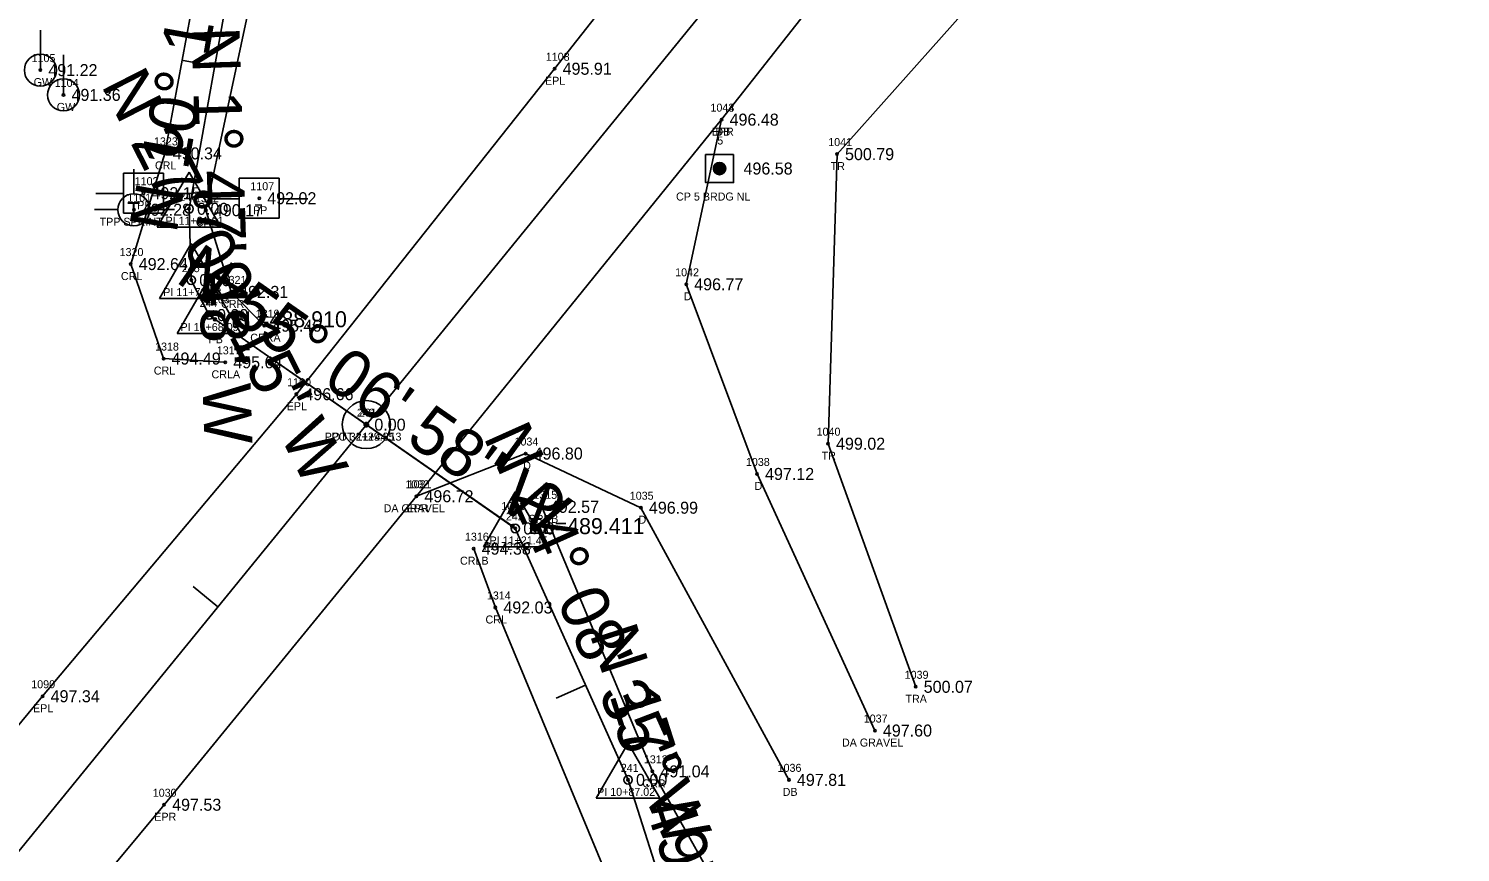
# Model space of a CAD drawing. Extents: x 1649047 to 1650429, y 896228 to 898747.
# Drawn here: x 1649581.4 to 1649760.2, y 896937.8 to 897040.7 of the extents above; entities that cross this region are included whole.
import ezdxf

# ---------------------------------------------------------------- set-up
doc = ezdxf.new("R2010")
doc.units = 0
for name, color, linetype in [('RD_EX_DR_Pipe', 7, 'Continuous'), ('RD_EX_DR_Pipe_txCode', 7, 'Continuous'), ('RD_EX_Driveway', 7, 'Continuous'), ('RD_EX_Driveway_txCode', 7, 'Continuous'), ('RD_EX_H2O', 7, 'Continuous'), ('RD_EX_H2O_txCode', 7, 'Continuous'), ('RD_EX_Road', 7, 'Continuous'), ('RD_EX_Road_txCode', 7, 'Continuous'), ('RD_EX_TX_Driveway_ELEV', 7, 'Continuous'), ('RD_EX_TX_H2O_ELEV', 7, 'Continuous'), ('RD_EX_TX_Road_ELEV', 7, 'Continuous'), ('RD_EX_TX_UT_ELEV', 7, 'Continuous'), ('RD_EX_TX_VEG_ELEV', 7, 'Continuous'), ('RD_EX_UT', 7, 'Continuous'), ('RD_EX_UT_txCode', 7, 'Continuous'), ('RD_EX_VEG', 7, 'Continuous'), ('RD_EX_VEG_txCode', 7, 'Continuous'), ('RD_HC_Cl', 7, 'Continuous'), ('RD_HC_Data', 7, 'Continuous'), ('RD_HC_Data_Tic', 7, 'Continuous'), ('RD_HC_Survey', 7, 'Continuous'), ('RD_HC_Survey_ELEV', 7, 'Continuous'), ('RD_HC_Survey_txCode', 7, 'Continuous'), ('RD_HC_txCode', 7, 'Continuous'), ('RD_SMD_Locator', 7, 'Continuous'), ('RD_TX_Pipe_ElevEX', 7, 'Continuous')]:
    doc.layers.add(name, color=color, linetype=linetype)

msp = doc.modelspace()

# ---------------------------------------------------------------- linework, layer by layer
at = {"layer": 'RD_EX_DR_Pipe'}
msp.add_line((1649641.79, 896978.53), (1649604.61, 897004.38), dxfattribs=at)
at = {"layer": 'RD_EX_Driveway'}
for points in [[(1649687.07, 896952.98), (1649672.35, 896985.05), (1649663.5, 897008.75), (1649667.92, 897029.33)], [(1649629.8, 896982.26), (1649643.44, 896987.6), (1649657.84, 896980.83), (1649676.33, 896946.82)]]:
    msp.add_lwpolyline(points, dxfattribs=at)
at = {"layer": 'RD_EX_H2O'}
for points in [[(1649610.78, 897003.58), (1649606.65, 897007.8), (1649603.49, 897018.01), (1649613.66, 897065.71), (1649613.8, 897087.62), (1649648.77, 897123.4), (1649673.15, 897145.36), (1649677.84, 897170.04), (1649704.36, 897195), (1649732.98, 897211.32), (1649741.05, 897244.13), (1649760.18, 897240.39), (1649790.48, 897304.8), (1649814.66, 897340.98), (1649827.92, 897366.62), (1649835.63, 897392.05), (1649839.2, 897413.36), (1649851.88, 897417.91), (1649868.27, 897424.7)], [(1649605.92, 896999), (1649598.21, 896999.47), (1649594.11, 897011.28), (1649598.36, 897025.11), (1649605.96, 897065.98), (1649602.09, 897085.85), (1649642.84, 897130.64), (1649663.84, 897157.19), (1649669.86, 897175.88), (1649698.27, 897205.65), (1649723.06, 897216.5), (1649737.55, 897250.43)], [(1649658.37, 896863.91), (1649669.84, 896889.64), (1649670.89, 896919.23), (1649670.15, 896928.46), (1649659.28, 896947.88), (1649645.47, 896980.94)], [(1649644.34, 896865.88), (1649660.29, 896893.32), (1649657.16, 896926.24), (1649639.66, 896968.36), (1649636.95, 896975.71)]]:
    msp.add_lwpolyline(points, dxfattribs=at)
at = {"layer": 'RD_EX_Road'}
for points in [[(1649459.38, 896805.71), (1649486.55, 896839.62), (1649513.65, 896873.34), (1649538.22, 896902.56), (1649549.43, 896916.62), (1649583.1, 896957.27), (1649614.8, 896995.02), (1649647.06, 897035.69), (1649677.62, 897074.51), (1649708.33, 897114.44), (1649735.5, 897151.61), (1649762.11, 897192.19), (1649788.21, 897235.29), (1649812.17, 897279.73), (1649834.32, 897326.54), (1649852.94, 897371.82), (1649867.51, 897411.96)], [(1649474.75, 896792.65), (1649502.78, 896827.35), (1649565.2, 896903.92), (1649598.28, 896943.71), (1649629.8, 896982.26), (1649667.92, 897029.33), (1649693.13, 897061.44), (1649723.58, 897101.84), (1649752.37, 897141.09), (1649779.72, 897182.3), (1649806.12, 897225.84), (1649830.13, 897270.79), (1649852.39, 897317.43), (1649871.98, 897364.35), (1649886.55, 897406.09)]]:
    msp.add_lwpolyline(points, dxfattribs=at)
at = {"layer": 'RD_EX_UT'}
for p, q in [((1649582.82, 897035.52), (1649582.82, 897040.52)), ((1649585.71, 897032.42), (1649585.71, 897037.42)), ((1649594.5, 897023.14), (1649594.5, 897020.07)), ((1649598.19, 897022.65), (1649593.19, 897022.65)), ((1649593.19, 897022.65), (1649593.19, 897017.65)), ((1649598.19, 897017.65), (1649598.19, 897022.65)), ((1649612.65, 897022.02), (1649607.65, 897022.02)), ((1649607.65, 897022.02), (1649607.65, 897017.02)), ((1649612.65, 897017.02), (1649612.65, 897022.02)), ((1649589.76, 897020.09), (1649593.23, 897020.09)), ((1649598.12, 897020.09), (1649601.76, 897020.09)), ((1649604.22, 897019.45), (1649607.69, 897019.45)), ((1649612.58, 897019.45), (1649616.22, 897019.45)), ((1649589.57, 897018.09), (1649592.5, 897018.09)), ((1649593.19, 897017.65), (1649598.19, 897017.65)), ((1649596.5, 897018.09), (1649599.57, 897018.09)), ((1649607.65, 897017.02), (1649612.65, 897017.02))]:
    msp.add_line(p, q, dxfattribs=at)
for centre in [(1649582.82, 897035.52), (1649585.71, 897032.42), (1649594.5, 897018.07)]:
    msp.add_circle(centre, 2, dxfattribs=at)
at = {"layer": 'RD_EX_VEG'}
msp.add_lwpolyline([(1649692.17, 896958.45), (1649681.22, 896988.83), (1649682.34, 897025.02), (1649740.01, 897089.71), (1649819.17, 897217.64), (1649850.28, 897262.86), (1649861.15, 897270.14), (1649933.62, 897283.21)], dxfattribs=at)
at = {"layer": 'RD_HC_Cl'}
for p, q in [((1649309.97, 896606.4), (1649686.99, 897069.08)), ((1649601.39, 897018.19), (1649610.06, 897066.5)), ((1649601.67, 897009.27), (1649601.39, 897018.19)), ((1649603.89, 897004.91), (1649601.67, 897009.27)), ((1649642.15, 896978.24), (1649603.89, 897004.91)), ((1649656.23, 896946.82), (1649642.15, 896978.24)), ((1649662.63, 896926.92), (1649656.23, 896946.82))]:
    msp.add_line(p, q, dxfattribs=at)
at = {"layer": 'RD_HC_Data'}
for p, q in [((1649597.42, 897015.9), (1649601.39, 897022.78)), ((1649601.39, 897022.78), (1649605.36, 897015.9)), ((1649597.42, 897015.9), (1649605.36, 897015.9)), ((1649597.7, 897006.98), (1649601.67, 897013.85)), ((1649601.67, 897013.85), (1649605.64, 897006.98)), ((1649599.92, 897002.62), (1649603.89, 897009.5)), ((1649603.89, 897009.5), (1649607.86, 897002.62)), ((1649597.7, 897006.98), (1649605.64, 897006.98)), ((1649599.92, 897002.62), (1649607.86, 897002.62)), ((1649638.18, 896975.94), (1649642.15, 896982.82)), ((1649642.15, 896982.82), (1649646.12, 896975.94)), ((1649638.18, 896975.94), (1649646.12, 896975.94)), ((1649652.26, 896944.53), (1649656.23, 896951.41)), ((1649656.23, 896951.41), (1649660.2, 896944.53)), ((1649652.26, 896944.53), (1649660.2, 896944.53))]:
    msp.add_line(p, q, dxfattribs=at)
for centre, radius in [((1649601.39, 897018.19), 0.529), ((1649601.67, 897009.27), 0.529), ((1649603.89, 897004.91), 0.529), ((1649623.54, 896991.21), 3), ((1649623.54, 896991.21), 3), ((1649623.54, 896991.21), 0.282), ((1649623.54, 896991.21), 0.282), ((1649642.15, 896978.24), 0.529), ((1649656.23, 896946.82), 0.529)]:
    msp.add_circle(centre, radius, dxfattribs=at)
at = {"layer": 'RD_HC_Data_Tic'}
for p, q in [((1649604.58, 897036), (1649600.65, 897036.71)), ((1649605, 896968.46), (1649601.9, 896970.99)), ((1649650.92, 896958.67), (1649647.27, 896957.03))]:
    msp.add_line(p, q, dxfattribs=at)
at = {"layer": 'RD_HC_Survey'}
for p, q in [((1649666.91, 897023.04), (1649666.91, 897023.4)), ((1649666.94, 897022.96), (1649666.94, 897023.48)), ((1649666.96, 897022.9), (1649666.96, 897023.54)), ((1649666.99, 897022.85), (1649666.99, 897023.59)), ((1649667.01, 897022.81), (1649667.01, 897023.63)), ((1649667.03, 897022.77), (1649667.03, 897023.67)), ((1649667.06, 897022.74), (1649667.06, 897023.7)), ((1649667.08, 897022.71), (1649667.08, 897023.73)), ((1649667.11, 897022.68), (1649667.11, 897023.76)), ((1649667.13, 897022.66), (1649667.13, 897023.78)), ((1649667.16, 897022.64), (1649667.16, 897023.8)), ((1649667.18, 897022.62), (1649667.18, 897023.82)), ((1649667.21, 897022.6), (1649667.21, 897023.84)), ((1649667.23, 897022.58), (1649667.23, 897023.86)), ((1649667.26, 897022.56), (1649667.26, 897023.88)), ((1649667.28, 897022.55), (1649667.28, 897023.89)), ((1649667.31, 897022.54), (1649667.31, 897023.9)), ((1649667.33, 897022.52), (1649667.33, 897023.92)), ((1649667.36, 897022.51), (1649667.36, 897023.93)), ((1649667.38, 897022.5), (1649667.38, 897023.94)), ((1649667.41, 897022.49), (1649667.41, 897023.95)), ((1649667.43, 897022.49), (1649667.43, 897023.96)), ((1649667.46, 897022.48), (1649667.46, 897023.96)), ((1649667.48, 897022.47), (1649667.48, 897023.97)), ((1649667.5, 897022.47), (1649667.5, 897023.97)), ((1649667.53, 897022.46), (1649667.53, 897023.98)), ((1649667.55, 897022.46), (1649667.55, 897023.98)), ((1649667.58, 897022.46), (1649667.58, 897023.99)), ((1649667.6, 897022.45), (1649667.6, 897023.99)), ((1649667.63, 897022.45), (1649667.63, 897023.99)), ((1649667.65, 897022.45), (1649667.65, 897023.99)), ((1649667.68, 897022.45), (1649667.68, 897023.99)), ((1649667.7, 897022.45), (1649667.7, 897023.99)), ((1649667.73, 897022.45), (1649667.73, 897023.99)), ((1649667.75, 897022.46), (1649667.75, 897023.98)), ((1649667.78, 897022.46), (1649667.78, 897023.98)), ((1649667.8, 897022.46), (1649667.8, 897023.98)), ((1649667.83, 897022.47), (1649667.83, 897023.97)), ((1649667.85, 897022.48), (1649667.85, 897023.97)), ((1649667.88, 897022.48), (1649667.88, 897023.96)), ((1649667.9, 897022.49), (1649667.9, 897023.95)), ((1649667.93, 897022.5), (1649667.93, 897023.94)), ((1649667.95, 897022.51), (1649667.95, 897023.93)), ((1649667.98, 897022.52), (1649667.98, 897023.92)), ((1649668, 897022.53), (1649668, 897023.91)), ((1649668.02, 897022.54), (1649668.02, 897023.9)), ((1649668.05, 897022.56), (1649668.05, 897023.88)), ((1649668.07, 897022.57), (1649668.07, 897023.87)), ((1649668.1, 897022.59), (1649668.1, 897023.85)), ((1649668.12, 897022.61), (1649668.12, 897023.83)), ((1649668.15, 897022.63), (1649668.15, 897023.81)), ((1649668.17, 897022.65), (1649668.17, 897023.79)), ((1649668.2, 897022.67), (1649668.2, 897023.77)), ((1649668.22, 897022.7), (1649668.22, 897023.74)), ((1649668.25, 897022.72), (1649668.25, 897023.72)), ((1649668.27, 897022.76), (1649668.27, 897023.69)), ((1649668.3, 897022.79), (1649668.3, 897023.65)), ((1649668.32, 897022.83), (1649668.32, 897023.61)), ((1649668.35, 897022.87), (1649668.35, 897023.57)), ((1649668.37, 897022.93), (1649668.37, 897023.51)), ((1649668.4, 897023), (1649668.4, 897023.44)), ((1649668.42, 897023.11), (1649668.42, 897023.33))]:
    msp.add_line(p, q, dxfattribs=at)
msp.add_lwpolyline([(1649669.41, 897024.97), (1649665.91, 897024.97), (1649665.91, 897021.47), (1649669.41, 897021.47)], close=True, dxfattribs=at)
msp.add_circle((1649667.66, 897023.22), 0.769, dxfattribs=at)
at = {"layer": 'RD_SMD_Locator'}
for centre, radius in [((1649582.82, 897035.52), 0.15), ((1649647.06, 897035.69), 0.15), ((1649585.71, 897032.42), 0.15), ((1649667.92, 897029.33), 0.15), ((1649667.92, 897029.33), 0.15), ((1649598.36, 897025.11), 0.15), ((1649682.34, 897025.02), 0.15), ((1649667.66, 897023.22), 0.15), ((1649595.7, 897020.14), 0.15), ((1649610.16, 897019.51), 0.15), ((1649594.5, 897018.07), 0.15), ((1649601.39, 897018.19), 0.15), ((1649603.49, 897018.01), 0.15), ((1649594.11, 897011.28), 0.15), ((1649601.67, 897009.27), 0.15), ((1649663.5, 897008.75), 0.15), ((1649606.65, 897007.8), 0.15), ((1649603.89, 897004.91), 0.15), ((1649604.61, 897004.38), 0.2), ((1649610.78, 897003.58), 0.15), ((1649598.21, 896999.47), 0.15), ((1649605.92, 896999), 0.15), ((1649614.8, 896995.02), 0.15), ((1649623.54, 896991.21), 0.15), ((1649623.54, 896991.21), 0.15), ((1649681.22, 896988.83), 0.15), ((1649643.44, 896987.6), 0.15), ((1649672.35, 896985.05), 0.15), ((1649629.8, 896982.26), 0.15), ((1649629.8, 896982.26), 0.15), ((1649645.47, 896980.94), 0.15), ((1649657.84, 896980.83), 0.15), ((1649641.79, 896978.53), 0.2), ((1649642.15, 896978.24), 0.15), ((1649636.95, 896975.71), 0.15), ((1649639.66, 896968.36), 0.15), ((1649692.17, 896958.45), 0.15), ((1649583.1, 896957.27), 0.15), ((1649687.07, 896952.98), 0.15), ((1649659.28, 896947.88), 0.15), ((1649656.23, 896946.82), 0.15), ((1649676.33, 896946.82), 0.15), ((1649598.28, 896943.71), 0.15)]:
    msp.add_circle(centre, radius, dxfattribs=at)

# ---------------------------------------------------------------- texts
at = {"layer": 'RD_EX_DR_Pipe_txCode'}
for s, p in [('1103', (1649603.51, 897006.38)), ('PB', (1649603.83, 897001.38)), ('1033', (1649640.4, 896980.53)), ('PA 72 RC', (1649638.21, 896975.53))]:
    msp.add_text(s, height=1, dxfattribs=at).set_placement(p)
at = {"layer": 'RD_EX_Driveway_txCode'}
for s, p in [('1043', (1649666.53, 897030.33)), ('DB', (1649667.14, 897027.33)), ('1042', (1649662.12, 897009.75)), ('D', (1649663.19, 897006.75)), ('1034', (1649642.05, 896988.6)), ('1038', (1649670.96, 896986.05)), ('D', (1649643.13, 896985.6)), ('1032', (1649628.42, 896983.26)), ('D', (1649672.04, 896983.05)), ('1035', (1649656.45, 896981.83)), ('DA GRAVEL', (1649625.7, 896980.26)), ('D', (1649657.53, 896978.83)), ('1037', (1649685.68, 896953.98)), ('DA GRAVEL', (1649682.96, 896950.98)), ('1036', (1649674.92, 896947.82)), ('DB', (1649675.55, 896944.82))]:
    msp.add_text(s, height=1, dxfattribs=at).set_placement(p)
at = {"layer": 'RD_EX_H2O_txCode'}
for s, p in [('1323', (1649597.01, 897026.11)), ('CRL', (1649597.13, 897023.11)), ('1322', (1649602.14, 897019.01)), ('CRR', (1649602.24, 897016.01)), ('1320', (1649592.72, 897012.28)), ('CRL', (1649592.88, 897009.28)), ('1321', (1649605.59, 897008.8)), ('CRR', (1649605.4, 897005.8)), ('1319', (1649609.72, 897004.58)), ('1318', (1649597.15, 897000.47)), ('CRRA', (1649609.04, 897001.58)), ('1317', (1649604.86, 897000)), ('CRL', (1649596.99, 896997.47)), ('CRLA', (1649604.2, 896997)), ('1315', (1649644.4, 896981.94)), ('CRRB', (1649643.74, 896978.94)), ('1316', (1649635.86, 896976.71)), ('CRLB', (1649635.24, 896973.71)), ('1314', (1649638.6, 896969.36)), ('CRL', (1649638.43, 896966.36)), ('1313', (1649658.21, 896948.88)), ('CRR', (1649658.02, 896945.88))]:
    msp.add_text(s, height=1, dxfattribs=at).set_placement(p)
at = {"layer": 'RD_EX_Road_txCode'}
for s, p in [('1108', (1649645.96, 897036.69)), ('EPL', (1649645.86, 897033.69)), ('1044', (1649666.53, 897030.33)), ('EPR', (1649666.69, 897027.33)), ('1100', (1649613.65, 896996.02)), ('EPL', (1649613.59, 896993.02)), ('1031', (1649628.7, 896983.26)), ('EPR', (1649628.57, 896980.26)), ('1090', (1649581.68, 896958.27)), ('EPL', (1649581.9, 896955.27)), ('1030', (1649596.86, 896944.71)), ('EPR', (1649597.05, 896941.71))]:
    msp.add_text(s, height=1, dxfattribs=at).set_placement(p)
at = {"layer": 'RD_EX_TX_Driveway_ELEV'}
for s, p in [('496.48', (1649668.92, 897028.58)), ('496.77', (1649664.5, 897008)), ('496.80', (1649644.44, 896986.85)), ('497.12', (1649673.35, 896984.3)), ('496.72', (1649630.8, 896981.51)), ('496.99', (1649658.84, 896980.08)), ('497.60', (1649688.07, 896952.23)), ('497.81', (1649677.33, 896946.07))]:
    msp.add_text(s, height=1.5, dxfattribs=at).set_placement(p)
at = {"layer": 'RD_EX_TX_H2O_ELEV'}
for s, p in [('490.34', (1649599.36, 897024.36)), ('490.17', (1649604.49, 897017.26)), ('492.64', (1649595.11, 897010.53)), ('492.31', (1649607.65, 897007.05)), ('495.46', (1649611.78, 897002.83)), ('494.49', (1649599.21, 896998.72)), ('495.64', (1649606.92, 896998.25)), ('492.57', (1649646.47, 896980.19)), ('494.38', (1649637.95, 896974.96)), ('492.03', (1649640.66, 896967.61)), ('491.04', (1649660.28, 896947.13))]:
    msp.add_text(s, height=1.5, dxfattribs=at).set_placement(p)
at = {"layer": 'RD_EX_TX_Road_ELEV'}
for s, p in [('495.91', (1649648.06, 897034.94)), ('496.48', (1649668.92, 897028.58)), ('496.66', (1649615.8, 896994.27)), ('496.72', (1649630.8, 896981.51)), ('497.34', (1649584.1, 896956.52)), ('497.53', (1649599.28, 896942.96))]:
    msp.add_text(s, height=1.5, dxfattribs=at).set_placement(p)
at = {"layer": 'RD_EX_TX_UT_ELEV'}
for s, p in [('491.22', (1649583.82, 897034.77)), ('491.36', (1649586.71, 897031.67)), ('492.28', (1649595.5, 897017.32))]:
    msp.add_text(s, height=1.5, dxfattribs=at).set_placement(p)
at = {"layer": 'RD_EX_TX_VEG_ELEV'}
for s, p in [('500.79', (1649683.34, 897024.27)), ('499.02', (1649682.22, 896988.08)), ('500.07', (1649693.17, 896957.7))]:
    msp.add_text(s, height=1.5, dxfattribs=at).set_placement(p)
at = {"layer": 'RD_EX_UT'}
msp.add_text('T', height=2, dxfattribs=at).set_placement((1649593.65, 897017.02))
at = {"layer": 'RD_EX_UT_txCode'}
for s, p in [('1105', (1649581.72, 897036.52)), ('GW', (1649581.98, 897033.52)), ('1104', (1649584.61, 897033.42)), ('GW', (1649584.87, 897030.42)), ('1102', (1649594.6, 897021.14)), ('1107', (1649609.05, 897020.51)), ('1101', (1649593.68, 897019.07)), ('PP', (1649594.92, 897018.14)), ('PP', (1649609.38, 897017.51)), ('TPP SPRINT', (1649590.22, 897016.07))]:
    msp.add_text(s, height=1, dxfattribs=at).set_placement(p)
at = {"layer": 'RD_EX_VEG_txCode'}
for s, p in [('1041', (1649681.24, 897026.02)), ('TR', (1649681.55, 897023.02)), ('1040', (1649679.79, 896989.83)), ('TR', (1649680.42, 896986.83)), ('1039', (1649690.79, 896959.45)), ('TRA', (1649690.89, 896956.45))]:
    msp.add_text(s, height=1, dxfattribs=at).set_placement(p)
at = {"layer": 'RD_HC_Data'}
for s, rotation, p in [('N 10%%d 10\' 24" E', 79.8265, (1649599.8, 897014.98)), ('N 1%%d 47\' 48" W', 271.7966, (1649601.68, 897040.87)), ('N 27%%d 00\' 15" W', 297.0043, (1649590.35, 897033.67)), ('N 55%%d 06\' 58" W', 325.1162, (1649599.54, 897009.16)), ('N 24%%d 08\' 35" W', 294.143, (1649638.11, 896989.7)), ('N 17%%d 49\' 56" W', 287.8321, (1649651.4, 896965.09))]:
    msp.add_text(s, height=6, rotation=rotation, dxfattribs=at).set_placement(p)
at = {"layer": 'RD_HC_Survey_ELEV'}
for s, p in [('496.58', (1649670.66, 897022.47)), ('492.15', (1649596.7, 897019.39)), ('492.02', (1649611.16, 897018.76)), ('0.00', (1649602.39, 897017.44)), ('0.00', (1649602.67, 897008.52)), ('0.00', (1649604.89, 897004.16)), ('0.00', (1649624.54, 896990.46)), ('0.00', (1649624.54, 896990.46)), ('0.00', (1649643.15, 896977.49)), ('0.00', (1649657.23, 896946.07))]:
    msp.add_text(s, height=1.5, dxfattribs=at).set_placement(p)
at = {"layer": 'RD_HC_Survey_txCode'}
for s, p in [('5', (1649667.38, 897026.22)), ('CP 5 BRDG NL', (1649662.23, 897019.22))]:
    msp.add_text(s, height=1, dxfattribs=at).set_placement(p)
at = {"layer": 'RD_HC_txCode'}
for s, p in [('246', (1649600.18, 897019.19)), ('PI 11+81.91', (1649598.46, 897016.19)), ('245', (1649600.49, 897010.27)), ('PI 11+72.98', (1649598.17, 897007.27)), ('244', (1649602.71, 897005.91)), ('PI 11+68.09', (1649600.33, 897002.91)), ('243', (1649622.36, 896992.21)), ('201', (1649622.6, 896992.21)), ('POT 32+29.35', (1649618.34, 896989.21)), ('POT 11+44.13', (1649619.19, 896989.21)), ('242', (1649640.97, 896979.24)), ('PI 11+21.45', (1649638.94, 896976.24)), ('241', (1649655.33, 896947.82)), ('PI 10+87.02', (1649652.37, 896944.82))]:
    msp.add_text(s, height=1, dxfattribs=at).set_placement(p)
at = {"layer": 'RD_TX_Pipe_ElevEX'}
for s, p in [('EL=488.910', (1649606.61, 897003.38)), ('EL=489.411', (1649643.79, 896977.53))]:
    msp.add_text(s, height=2, dxfattribs=at).set_placement(p)

doc.saveas('drawing.dxf')
